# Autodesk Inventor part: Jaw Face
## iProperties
Shininess: 77.0
Length Units: 11269
Angle Units: 11279
Time Units: 11290
Mass Units: 11283
Length Display Precision: 3
Angle Display Precision: 2
Compacted: True
Created: 2002-02
Part Number: Jaw Face
Document SubType Name: Modeling
Designer: ***
Density: 1 g/cm^3
Density: 0.0
Volumn: 0.0
Area: 0.0
PropertySet Name: Model Information
Control State: 0
Master: False
Checked Out: False
Author: ***
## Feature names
1. Extrusion1
